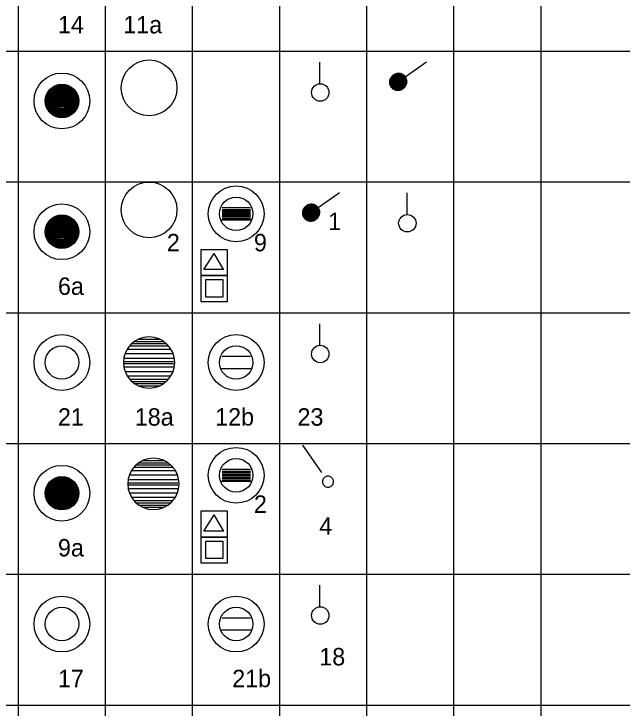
# Model space of a CAD drawing. Extents: x -28 to 822, y 61 to 665.
# Drawn here: x 122.6 to 192.5, y 141.4 to 221 of the extents above; entities that cross this region are included whole.
import ezdxf

# ---------------------------------------------------------------- set-up
doc = ezdxf.new("R2010")
doc.units = 0
doc.layers.add('KOLEJIŠTĚ', color=7, linetype='Continuous')

# ---------------------------------------------------------------- blocks, each defined once
blk = doc.blocks.new('HR6')
for p, q in [((-1.304, 1.895), (1.304, 1.895)), ((-0.95, 2.095), (0.95, 2.095)), ((-1.748, 1.495), (1.748, 1.495)), ((-1.555, 1.695), (1.555, 1.695)), ((-2.156, 0.8), (2.156, 0.8)), ((-1.962, 1.2), (1.962, 1.2)), ((-2.265, 0.4), (2.265, 0.4)), ((-2.2, 0.09), (2.2, 0.09)), ((-2.265, -0.4), (2.265, -0.4)), ((-2.2, -0.09), (2.2, -0.09)), ((-2.156, -0.8), (2.156, -0.8)), ((-1.962, -1.2), (1.962, -1.2)), ((-1.748, -1.495), (1.748, -1.495)), ((-1.555, -1.695), (1.555, -1.695)), ((-1.304, -1.895), (1.304, -1.895)), ((-0.95, -2.095), (0.95, -2.095))]:
    blk.add_line(p, q)
for start, end in [(0, 180), (180, 0)]:
    blk.add_arc((0, 0), 2.3, start, end)
blk = doc.blocks.new('ZT75')
at = {"xscale": 0.8, "yscale": 0.8000000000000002}
blk.add_blockref('HR6', (0, 0), dxfattribs=at)
blk = doc.blocks.new('HR3')
for radius in [2.5, 1.5]:
    blk.add_circle((0, 0), radius)
blk = doc.blocks.new('ZT72')
at = {"xscale": 0.8, "yscale": 0.8000000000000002}
blk.add_blockref('HR3', (0, 0), dxfattribs=at)
blk = doc.blocks.new('_X10')
for p, q in [((370.452, 480.16), (371.464, 481.172)), ((370.452, 480.177), (371.447, 481.172)), ((370.452, 480.195), (371.429, 481.172)), ((370.453, 480.142), (371.482, 481.172)), ((370.453, 480.125), (371.499, 481.171)), ((370.453, 480.214), (371.411, 481.171)), ((370.454, 480.109), (371.515, 481.17)), ((370.454, 480.232), (371.392, 481.17)), ((370.455, 480.092), (371.532, 481.169)), ((370.455, 480.251), (371.373, 481.169)), ((370.457, 480.076), (371.548, 481.167)), ((370.457, 480.271), (371.353, 481.167)), ((370.458, 480.06), (371.564, 481.166)), ((370.459, 480.291), (371.334, 481.165)), ((370.46, 480.044), (371.58, 481.164)), ((370.462, 480.029), (371.596, 481.162)), ((370.462, 480.311), (371.313, 481.162)), ((370.465, 480.013), (371.611, 481.159)), ((370.465, 480.332), (371.293, 481.159)), ((370.467, 479.998), (371.626, 481.157)), ((370.469, 480.353), (371.271, 481.156)), ((370.47, 479.983), (371.641, 481.154)), ((370.473, 479.969), (371.656, 481.151)), ((370.473, 480.375), (371.249, 481.151)), ((370.476, 479.954), (371.67, 481.148)), ((370.478, 480.398), (371.227, 481.146)), ((370.479, 479.94), (371.685, 481.145)), ((370.483, 479.925), (371.699, 481.141)), ((370.484, 480.421), (371.203, 481.141)), ((370.487, 479.911), (371.713, 481.137)), ((370.49, 480.445), (371.179, 481.134)), ((370.491, 479.898), (371.727, 481.134)), ((370.495, 479.884), (371.74, 481.13)), ((370.498, 480.47), (371.154, 481.126)), ((370.499, 479.87), (371.754, 481.125)), ((370.503, 479.857), (371.767, 481.121)), ((370.506, 480.497), (371.127, 481.118)), ((370.507, 479.844), (371.78, 481.117)), ((370.512, 479.831), (371.793, 481.112)), ((370.516, 480.524), (371.1, 481.108)), ((370.517, 479.818), (371.806, 481.107)), ((370.522, 479.805), (371.819, 481.102)), ((370.527, 479.793), (371.832, 481.097)), ((370.528, 480.554), (371.071, 481.096)), ((370.532, 479.78), (371.844, 481.092)), ((370.537, 479.768), (371.856, 481.087)), ((370.541, 480.585), (371.039, 481.083)), ((370.543, 479.756), (371.869, 481.081)), ((370.549, 479.744), (371.881, 481.076)), ((370.554, 479.732), (371.893, 481.07)), ((370.557, 480.618), (371.006, 481.067)), ((370.56, 479.72), (371.904, 481.064)), ((370.566, 479.708), (371.916, 481.058)), ((370.572, 479.697), (371.928, 481.052)), ((370.577, 480.656), (370.968, 481.047)), ((370.579, 479.685), (371.939, 481.046)), ((370.585, 479.674), (371.95, 481.039)), ((370.592, 479.663), (371.961, 481.033)), ((370.598, 479.652), (371.972, 481.026)), ((370.602, 480.698), (370.926, 481.022)), ((370.605, 479.641), (371.983, 481.019)), ((370.612, 479.63), (371.994, 481.012)), ((370.619, 479.619), (372.005, 481.005)), ((370.626, 479.609), (372.015, 480.998)), ((370.633, 479.598), (372.026, 480.991)), ((370.637, 480.751), (370.873, 480.988)), ((370.64, 479.588), (372.036, 480.984)), ((370.648, 479.578), (372.046, 480.976)), ((370.655, 479.568), (372.057, 480.969)), ((370.663, 479.558), (372.067, 480.961)), ((370.671, 479.548), (372.076, 480.953)), ((370.679, 479.538), (372.086, 480.945)), ((370.687, 479.528), (372.096, 480.937)), ((370.695, 479.519), (372.105, 480.929)), ((370.703, 479.509), (372.115, 480.921)), ((370.706, 480.838), (370.786, 480.918)), ((370.712, 479.5), (372.124, 480.913)), ((370.72, 479.491), (372.133, 480.904)), ((370.729, 479.482), (372.142, 480.896)), ((370.737, 479.473), (372.151, 480.887)), ((370.746, 479.464), (372.16, 480.878)), ((370.755, 479.455), (372.169, 480.869)), ((370.764, 479.446), (372.178, 480.86)), ((370.773, 479.438), (372.186, 480.851)), ((370.782, 479.429), (372.195, 480.842)), ((370.792, 479.421), (372.203, 480.832)), ((370.801, 479.413), (372.211, 480.823)), ((370.811, 479.405), (372.219, 480.813)), ((370.821, 479.397), (372.227, 480.804)), ((370.83, 479.389), (372.235, 480.794)), ((370.84, 479.381), (372.243, 480.784)), ((370.85, 479.373), (372.251, 480.774)), ((370.86, 479.366), (372.258, 480.764)), ((370.871, 479.358), (372.266, 480.754)), ((370.881, 479.351), (372.273, 480.743)), ((370.891, 479.344), (372.28, 480.733)), ((370.902, 479.337), (372.287, 480.722)), ((370.913, 479.33), (372.294, 480.711)), ((370.924, 479.323), (372.301, 480.701)), ((370.935, 479.316), (372.308, 480.69)), ((370.946, 479.31), (372.314, 480.678)), ((370.957, 479.303), (372.321, 480.667)), ((370.968, 479.297), (372.327, 480.656)), ((370.98, 479.291), (372.333, 480.645)), ((370.991, 479.285), (372.34, 480.633)), ((371.003, 479.279), (372.346, 480.621)), ((371.015, 479.273), (372.351, 480.609)), ((371.027, 479.267), (372.357, 480.597)), ((371.039, 479.261), (372.363, 480.585)), ((371.051, 479.256), (372.368, 480.573)), ((371.063, 479.251), (372.373, 480.561)), ((371.076, 479.246), (372.379, 480.548)), ((371.089, 479.24), (372.384, 480.536)), ((371.101, 479.236), (372.389, 480.523)), ((371.114, 479.231), (372.393, 480.51)), ((371.127, 479.226), (372.398, 480.497)), ((371.141, 479.222), (372.402, 480.484)), ((371.154, 479.218), (372.407, 480.47)), ((371.167, 479.213), (372.411, 480.457)), ((371.181, 479.209), (372.415, 480.443)), ((371.195, 479.206), (372.419, 480.429)), ((371.209, 479.202), (372.422, 480.415)), ((371.223, 479.199), (372.426, 480.401)), ((371.238, 479.195), (372.429, 480.386)), ((371.252, 479.192), (372.432, 480.372)), ((371.267, 479.189), (372.435, 480.357)), ((371.282, 479.187), (372.438, 480.342)), ((371.297, 479.184), (372.44, 480.327)), ((371.313, 479.182), (372.442, 480.311)), ((371.328, 479.18), (372.444, 480.296)), ((371.344, 479.178), (372.446, 480.28)), ((371.36, 479.176), (372.448, 480.264)), ((371.376, 479.175), (372.449, 480.248)), ((371.393, 479.174), (372.45, 480.231)), ((371.41, 479.173), (372.451, 480.214)), ((371.427, 479.172), (372.452, 480.197)), ((371.444, 479.172), (372.452, 480.18)), ((371.462, 479.172), (372.452, 480.162)), ((371.48, 479.172), (372.452, 480.144)), ((371.498, 479.173), (372.451, 480.126)), ((371.517, 479.174), (372.45, 480.107)), ((371.536, 479.176), (372.449, 480.088)), ((371.556, 479.177), (372.447, 480.068)), ((371.576, 479.18), (372.444, 480.048)), ((371.596, 479.182), (372.442, 480.028)), ((371.617, 479.186), (372.438, 480.007)), ((371.639, 479.19), (372.435, 479.985)), ((371.661, 479.194), (372.43, 479.963)), ((371.684, 479.199), (372.425, 479.941)), ((371.707, 479.205), (372.419, 479.917)), ((371.732, 479.212), (372.412, 479.892)), ((371.757, 479.22), (372.404, 479.867)), ((371.784, 479.229), (372.395, 479.84)), ((371.812, 479.239), (372.385, 479.812)), ((371.841, 479.251), (372.373, 479.783)), ((371.873, 479.265), (372.359, 479.751)), ((371.908, 479.282), (372.342, 479.716)), ((371.946, 479.303), (372.322, 479.678)), ((371.991, 479.329), (372.295, 479.634)), ((372.047, 479.369), (372.256, 479.577))]:
    blk.add_line(p, q)

msp = doc.modelspace()

# ---------------------------------------------------------------- linework, layer by layer
for p, q in [((123.116, 381.738), (123.116, 111.738)), ((133.116, 381.738), (133.116, 141.738)), ((143.116, 381.738), (143.116, 141.738)), ((153.116, 381.738), (153.116, 111.738)), ((163.116, 381.738), (163.116, 111.738)), ((173.116, 381.738), (173.116, 111.738)), ((183.116, 381.738), (183.116, 111.738)), ((143.116, 366.738), (143.116, 111.738)), ((133.116, 336.738), (133.116, 111.738)), ((5.068, 216.738), (540.616, 216.738)), ((157.778, 212.941), (157.778, 215.474)), ((167.57, 213.796), (170.019, 215.529)), ((5.068, 201.738), (540.616, 201.738)), ((5.068, 201.738), (540.616, 201.738)), ((5.068, 201.738), (540.616, 201.738)), ((54.092, 201.738), (540.616, 201.738)), ((157.57, 198.796), (160.019, 200.529)), ((167.778, 197.941), (167.778, 200.474)), ((146.53, 198.794), (149.801, 198.794)), ((146.53, 198.571), (149.801, 198.571)), ((146.53, 198.433), (149.801, 198.433)), ((146.53, 198.273), (149.801, 198.273)), ((146.53, 198.114), (149.801, 198.114)), ((146.53, 198.05), (149.801, 198.05)), ((146.53, 197.885), (149.801, 197.885)), ((146.53, 197.726), (149.801, 197.726)), ((146.53, 197.543), (149.801, 197.543)), ((146.481, 197.409), (149.85, 197.409)), ((144.461, 191.699), (145.623, 193.552)), ((146.728, 191.672), (145.623, 193.552)), ((146.743, 191.699), (144.461, 191.699)), ((5.068, 186.738), (295.616, 186.738)), ((157.778, 182.941), (157.778, 185.474)), ((146.53, 181.738), (149.801, 181.738)), ((146.481, 180.353), (149.85, 180.353)), ((5.068, 171.738), (540.616, 171.738)), ((155.758, 171.558), (157.96, 168.412)), ((146.53, 168.794), (149.801, 168.794)), ((146.53, 168.571), (149.801, 168.571)), ((146.53, 168.433), (149.801, 168.433)), ((146.53, 168.273), (149.801, 168.273)), ((146.53, 168.114), (149.801, 168.114)), ((146.53, 168.05), (149.801, 168.05)), ((146.481, 167.409), (149.85, 167.409)), ((146.53, 167.885), (149.801, 167.885)), ((146.53, 167.726), (149.801, 167.726)), ((146.53, 167.543), (149.801, 167.543)), ((144.461, 161.699), (145.623, 163.552)), ((146.728, 161.672), (145.623, 163.552)), ((146.743, 161.699), (144.461, 161.699)), ((5.068, 156.738), (295.616, 156.738)), ((157.778, 152.941), (157.778, 155.474)), ((146.53, 151.738), (149.801, 151.738)), ((146.481, 150.353), (149.85, 150.353)), ((5.068, 141.738), (540.616, 141.738))]:
    msp.add_line(p, q)
for points in [[(129.101, 209.383), (127.208, 209.383), (127.208, 212.692), (129.101, 212.692)], [(128.937, 209.337), (127.326, 209.337), (127.326, 212.719), (128.937, 212.719)], [(128.764, 209.292), (127.472, 209.292), (127.472, 212.765), (128.764, 212.765)], [(128.609, 209.246), (127.645, 209.246), (127.645, 212.81), (128.609, 212.81)], [(128.455, 209.201), (127.836, 209.201), (127.836, 212.856), (128.455, 212.856)], [(129.829, 210.183), (126.471, 210.183), (126.471, 211.847), (129.829, 211.847)], [(129.802, 210.064), (126.507, 210.064), (126.507, 211.965), (129.802, 211.965)], [(129.683, 209.955), (126.571, 209.955), (126.571, 212.056), (129.683, 212.056)], [(129.592, 209.846), (126.698, 209.846), (126.698, 212.183), (129.592, 212.183)], [(129.465, 209.746), (126.799, 209.746), (126.799, 212.274), (129.465, 212.274)], [(129.365, 209.646), (126.89, 209.646), (126.89, 212.365), (129.365, 212.365)], [(129.274, 209.546), (126.971, 209.546), (126.971, 212.456), (129.274, 212.456)], [(129.165, 209.437), (127.072, 209.437), (127.072, 212.556), (129.165, 212.556)], [(130.047, 210.956), (126.28, 210.956), (126.28, 211.11), (130.047, 211.11)], [(129.984, 210.765), (126.307, 210.765), (126.307, 211.319), (129.984, 211.319)], [(130.011, 210.846), (126.307, 210.846), (126.307, 211.219), (130.011, 211.219)], [(129.965, 210.674), (126.353, 210.674), (126.353, 211.392), (129.965, 211.392)], [(129.938, 210.583), (126.371, 210.583), (126.371, 211.501), (129.938, 211.501)], [(129.911, 210.474), (126.407, 210.474), (126.407, 211.61), (129.911, 211.61)], [(129.874, 210.355), (126.435, 210.355), (126.435, 211.728), (129.874, 211.728)], [(129.165, 194.437), (127.072, 194.437), (127.072, 197.556), (129.165, 197.556)], [(129.101, 194.383), (127.208, 194.383), (127.208, 197.692), (129.101, 197.692)], [(128.937, 194.337), (127.326, 194.337), (127.326, 197.719), (128.937, 197.719)], [(128.764, 194.292), (127.472, 194.292), (127.472, 197.765), (128.764, 197.765)], [(128.609, 194.246), (127.645, 194.246), (127.645, 197.81), (128.609, 197.81)], [(128.455, 194.201), (127.836, 194.201), (127.836, 197.856), (128.455, 197.856)], [(129.874, 195.355), (126.435, 195.355), (126.435, 196.728), (129.874, 196.728)], [(129.829, 195.183), (126.471, 195.183), (126.471, 196.847), (129.829, 196.847)], [(129.802, 195.064), (126.507, 195.064), (126.507, 196.965), (129.802, 196.965)], [(129.683, 194.955), (126.571, 194.955), (126.571, 197.056), (129.683, 197.056)], [(129.592, 194.846), (126.698, 194.846), (126.698, 197.183), (129.592, 197.183)], [(129.465, 194.746), (126.799, 194.746), (126.799, 197.274), (129.465, 197.274)], [(129.365, 194.646), (126.89, 194.646), (126.89, 197.365), (129.365, 197.365)], [(129.274, 194.546), (126.971, 194.546), (126.971, 197.456), (129.274, 197.456)], [(130.047, 195.956), (126.28, 195.956), (126.28, 196.11), (130.047, 196.11)], [(129.984, 195.765), (126.307, 195.765), (126.307, 196.319), (129.984, 196.319)], [(130.011, 195.846), (126.307, 195.846), (126.307, 196.219), (130.011, 196.219)], [(129.965, 195.674), (126.353, 195.674), (126.353, 196.392), (129.965, 196.392)], [(129.938, 195.583), (126.371, 195.583), (126.371, 196.501), (129.938, 196.501)], [(129.911, 195.474), (126.407, 195.474), (126.407, 196.61), (129.911, 196.61)], [(147.139, 191), (144.139, 191), (144.139, 194), (147.139, 194)], [(147.139, 188), (144.139, 188), (144.139, 191), (147.139, 191)], [(146.618, 188.541), (144.691, 188.541), (144.691, 190.544), (146.618, 190.544)], [(129.465, 164.746), (126.799, 164.746), (126.799, 167.274), (129.465, 167.274)], [(129.365, 164.646), (126.89, 164.646), (126.89, 167.365), (129.365, 167.365)], [(129.274, 164.546), (126.971, 164.546), (126.971, 167.456), (129.274, 167.456)], [(129.165, 164.437), (127.072, 164.437), (127.072, 167.556), (129.165, 167.556)], [(129.101, 164.383), (127.208, 164.383), (127.208, 167.692), (129.101, 167.692)], [(128.937, 164.337), (127.326, 164.337), (127.326, 167.719), (128.937, 167.719)], [(128.764, 164.292), (127.472, 164.292), (127.472, 167.765), (128.764, 167.765)], [(128.609, 164.246), (127.645, 164.246), (127.645, 167.81), (128.609, 167.81)], [(128.455, 164.201), (127.836, 164.201), (127.836, 167.856), (128.455, 167.856)], [(129.938, 165.583), (126.371, 165.583), (126.371, 166.501), (129.938, 166.501)], [(129.911, 165.474), (126.407, 165.474), (126.407, 166.61), (129.911, 166.61)], [(129.874, 165.355), (126.435, 165.355), (126.435, 166.728), (129.874, 166.728)], [(129.829, 165.183), (126.471, 165.183), (126.471, 166.847), (129.829, 166.847)], [(129.802, 165.064), (126.507, 165.064), (126.507, 166.965), (129.802, 166.965)], [(129.683, 164.955), (126.571, 164.955), (126.571, 167.056), (129.683, 167.056)], [(129.592, 164.846), (126.698, 164.846), (126.698, 167.183), (129.592, 167.183)], [(130.047, 165.956), (126.28, 165.956), (126.28, 166.11), (130.047, 166.11)], [(129.984, 165.765), (126.307, 165.765), (126.307, 166.319), (129.984, 166.319)], [(130.011, 165.846), (126.307, 165.846), (126.307, 166.219), (130.011, 166.219)], [(129.965, 165.674), (126.353, 165.674), (126.353, 166.392), (129.965, 166.392)], [(147.139, 161), (144.139, 161), (144.139, 164), (147.139, 164)], [(147.139, 158), (144.139, 158), (144.139, 161), (147.139, 161)], [(146.618, 158.541), (144.691, 158.541), (144.691, 160.544), (146.618, 160.544)]]:
    msp.add_lwpolyline(points, close=True)
for centre, radius in [((138.157, 212.531), 3.2), ((157.81, 212.005), 1), ((138.157, 198.531), 3.2), ((167.81, 197.005), 1), ((157.81, 182.005), 1), ((157.81, 152.005), 1)]:
    msp.add_circle(centre, radius)
for start, end in [(35, 215), (215, 35)]:
    msp.add_arc((158.694, 167.363), 0.64, start, end)

# ---------------------------------------------------------------- block references
at = {"rotation": -92.29148628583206}
for p in [(-298.183, 603.572), (-308.183, 588.572)]:
    msp.add_blockref('_X10', p, dxfattribs=at)
at = {"xscale": 1.2800000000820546, "yscale": 1.2800000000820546}
for p in [(148.157, 198.087), (148.157, 181.031), (148.157, 168.087), (148.157, 151.031)]:
    msp.add_blockref('HR3', p, dxfattribs=at)
at = {"layer": 'KOLEJIŠTĚ', "xscale": 1.600000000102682, "yscale": 1.600000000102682}
for name, p in [('ZT72', (128.157, 211.031)), ('ZT72', (128.157, 196.031)), ('ZT72', (128.157, 181.031)), ('ZT75', (138.157, 181.031)), ('ZT75', (138.657, 167.106)), ('ZT72', (128.157, 166.031)), ('ZT72', (128.157, 151.031))]:
    msp.add_blockref(name, p, dxfattribs=at)

# ---------------------------------------------------------------- texts
for s, p in [('14', (127.698, 218.784)), ('11a', (135.198, 218.784)), ('1', (158.705, 196.219)), ('2', (140.198, 193.784)), ('9', (150.198, 193.784)), ('6a', (127.698, 188.784)), ('21', (127.698, 173.784)), ('18a', (136.518, 173.784)), ('12b', (145.747, 173.799)), ('23', (155.198, 173.784)), ('2', (150.198, 163.784)), ('4', (157.698, 161.284)), ('9a', (127.698, 158.784)), ('18', (157.698, 146.284)), ('17', (127.698, 143.784)), ('21b', (147.698, 143.784))]:
    msp.add_text(s, height=2).set_placement(p)

doc.saveas('drawing.dxf')
